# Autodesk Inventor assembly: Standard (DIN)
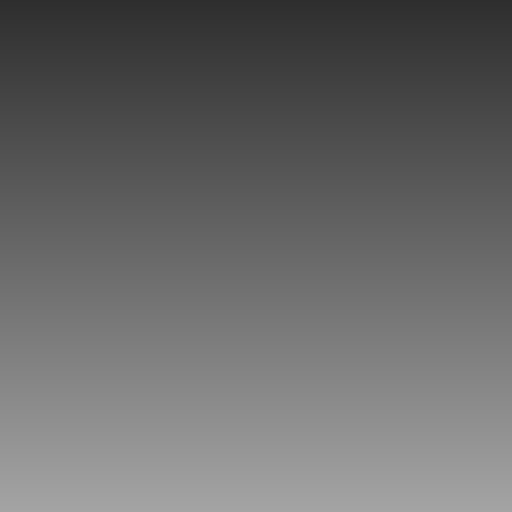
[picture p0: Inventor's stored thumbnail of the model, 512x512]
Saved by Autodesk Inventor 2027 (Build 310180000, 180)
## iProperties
Created: 2002-07
Part Number: Standard (DIN)
Document SubType Name: Assembly
Control State: 0
Master: False
Checked Out: False
Shininess: 64.0
Length Units: 11269
Angle Units: 11279
Time Units: 11290
Mass Units: 11283
Length Display Precision: 3
Angle Display Precision: 2
Compacted: True
Density: 0.0
Volumn: 0.0
Area: 0.0
PropertySet Name: Model Information
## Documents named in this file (1)
- D:\AUTOBUILD\inventor\Application\App\Templates\en-US\Metric\Standard (DIN).iam
